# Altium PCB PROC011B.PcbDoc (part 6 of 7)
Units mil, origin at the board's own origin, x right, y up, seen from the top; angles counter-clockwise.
Board outline 3304 x 2569 mil, 6 copper layers (TOP, L2-GND1, L3-GND/SIG, L4-GND/SIG, L5-GND2, BOTTOM), stack 55.77 mil thick; 376 components, 289 nets, 1284 pads, 1755 vias.
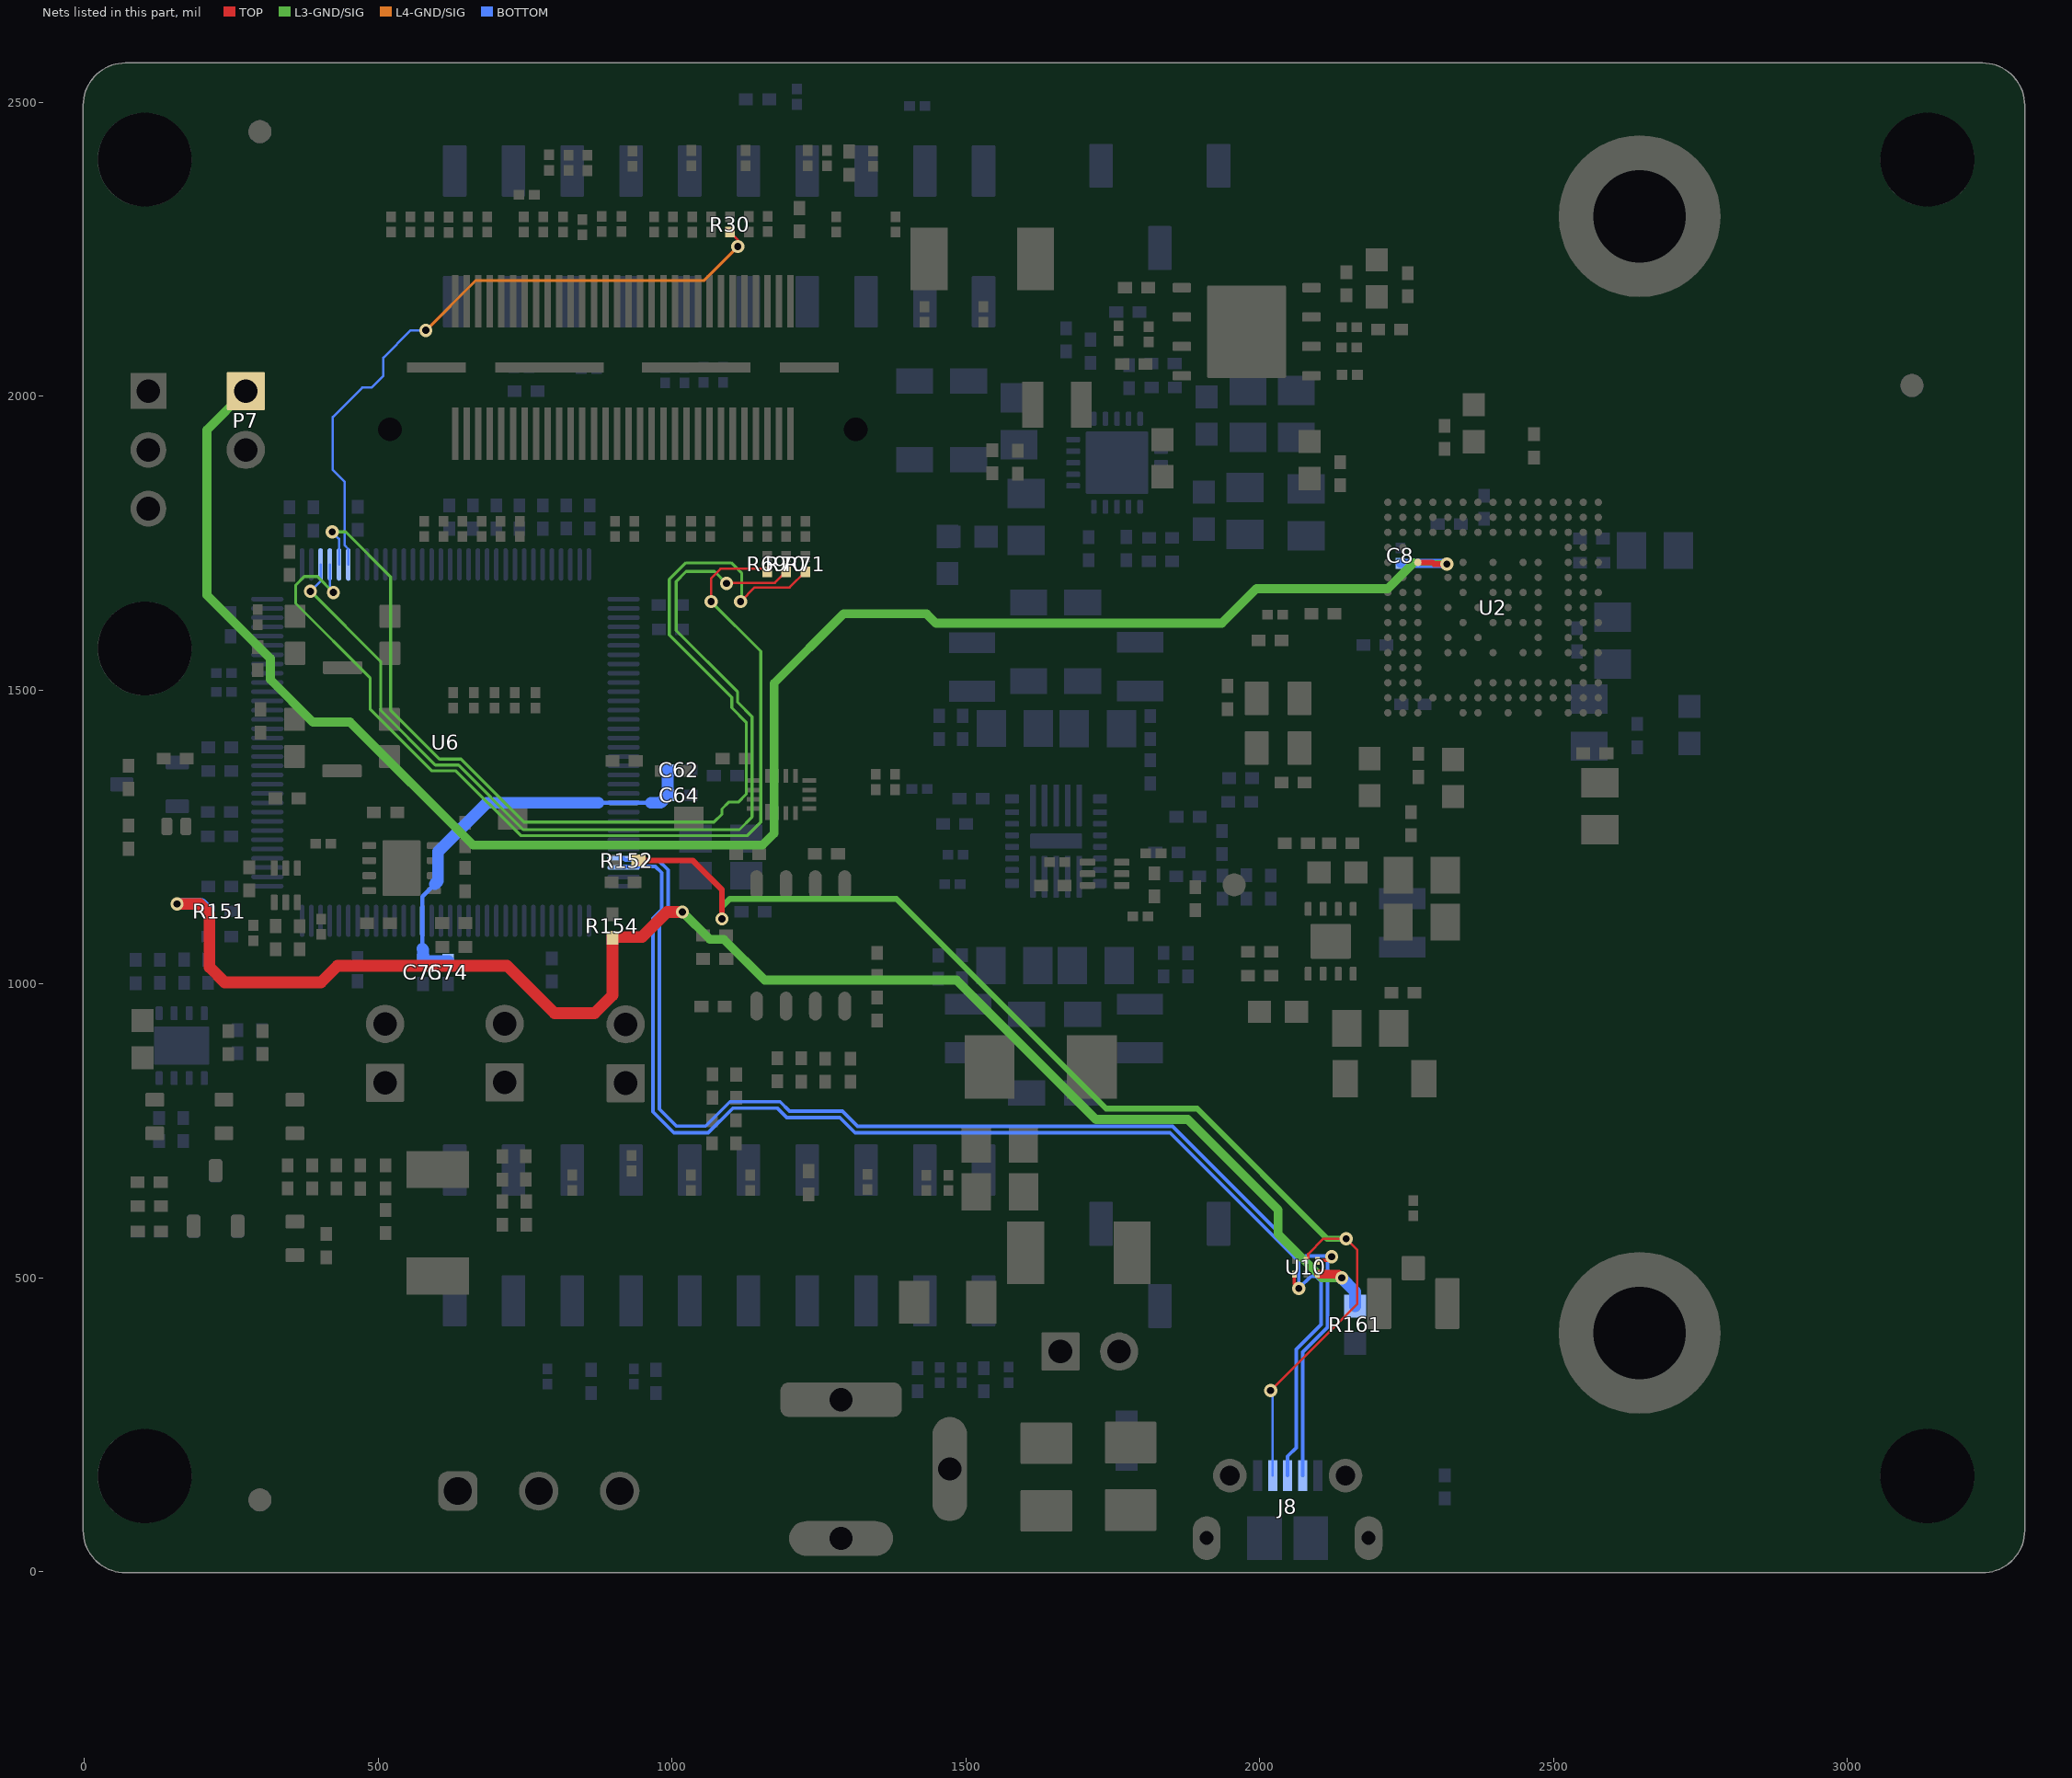
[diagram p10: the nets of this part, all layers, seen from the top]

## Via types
v1: diameter 22.4, hole 12.2, TOP to BOTTOM, tented both sides, 1046 vias
v2: diameter 13.77/15.74 (per signal layer), hole 5.9, TOP to L2-GND1, tented both sides, 699 vias
v3: diameter 19.68, hole 7.87, TOP to BOTTOM, tented both sides, 9 vias
v4: diameter 15.74, hole 5.9, TOP to L2-GND1, tented both sides, 1 vias

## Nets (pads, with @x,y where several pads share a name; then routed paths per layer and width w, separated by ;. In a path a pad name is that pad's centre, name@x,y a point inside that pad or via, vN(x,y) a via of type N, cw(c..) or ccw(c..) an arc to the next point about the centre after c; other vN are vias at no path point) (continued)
VDDC_1: C62.2 C64.2 C74.2 C75.2 U6.87 U6.115 | length 714.8
  BOTTOM w7: 575.17,1059.68 U6.115@575.17,1107.39 575.17,1148.62 596.35,1169.8 ; 874.57,1308.18 U6.87@917.69,1308.18 964.13,1308.18
  BOTTOM w20: 575.17,1059.68 576.43,1058.42 C75.2@576.43,1039.34 576.43,1038.95 C74.2@619.35,1038.95 ; 596.35,1169.8 601.75,1175.2 601.75,1224.9 685.03,1308.18 874.57,1308.18 ; 964.13,1308.18 980.48,1308.18 992.91,1320.61 993.1,1320.8 992.91,1320.99 992.8,1321.1 C62.2@992.8,1364
VPP_1P7: C8.2 P7.1 U2.L13 | length 3174.2
  TOP w10: U2.L13@2269.35,1717.17 2294.02,1717.17 2296.84,1714.35 v1(2318.74,1714.35)
  L3-GND/SIG w10: 2261.95,1716.3 2316.79,1716.3 v1(2318.74,1714.35)
  L3-GND/SIG w15: P7.1@274.69,2008.65 208.57,1942.53 208.57,1661.59 316.55,1553.61 316.55,1517.92 388.87,1445.6 452.05,1445.6 661.45,1236.2 1153.94,1236.2 1173.84,1256.1 1173.84,1511.71 1291.73,1629.6 1433.35,1629.6 1449.15,1613.8 1935.75,1613.8 1994.45,1672.5 2218.15,1672.5 2261.95,1716.3
  BOTTOM w15: C8.2@2239.75,1715.51 2317.59,1715.5 v1(2318.74,1714.35)
XDSET_1_D_N: J8.2 U6.93 U10.1 | length 2199.2
  TOP w5.2: U10.1@2098.44,529.81 2116.56,529.81 v1(2122.75,536)
  BOTTOM w6: U6.93@917.69,1213.69 920.38,1211 976.31,1211 993.45,1193.86 993.45,1121.69 985.21,1113.45 978.75,1106.99 978.75,787 1007.75,758 1057.25,758 1098.75,799.5 1184.01,799.5 1200.01,783.5 1290.31,783.5 1316.11,757.7 1852.05,757.7 2072.75,537 2121.75,537 v1(2122.75,536) 2115.75,529 2115.75,416 2073.34,373.59 J8.2@2073.34,163.38
XDSET_1_D_P: J8.3 U6.94 U10.4 | length 2198.8
  TOP w5.2: U10.4@2059.07,506.19 2059.06,489.69 v1(2066.75,482)
  BOTTOM w6: U6.94@917.69,1197.94 919.75,1200 971.75,1200 982.45,1189.3 982.45,1126.25 967.75,1111.55 967.75,782.44 1003.19,747 1061.81,747 1103.31,788.5 1179.45,788.5 1195.45,772.5 1285.75,772.5 1311.55,746.7 1847.49,746.7 2066.75,527.44 v1(2066.75,482) 2087.25,502.5 2095.75,502.5 2104.75,493.5 2104.75,420.56 2062.34,378.15 2062.34,210.8 2047.75,196.21 J8.3@2047.75,163.38
XDSET_1_ID: J8.4 R152.2 U10.2 | length 2101
  TOP w4: v1(2018.75,308) 2165.85,455.1 2165.85,547.9 v1(2147.25,566.5) 2108.75,566.5 2082.75,540.5 2082.75,533.81 U10.2@2078.75,529.81
  TOP w10: R152.2@942.99,1210 1035.15,1210 1084.95,1160.2 v1(1084.95,1110.55)
  L3-GND/SIG w10: v1(1084.95,1110.55) 1084.95,1131.2 1098.35,1144.6 1381.85,1144.6 1738.75,787.7 1893.55,787.7 2114.75,566.5 v1(2147.25,566.5)
  BOTTOM w4: v1(2018.75,308) 2022.16,304.59 J8.4@2022.16,163.38
XDSET_1_VBUS: R151.2 R154.2 R161.2 U10.6 | length 2710.2
  TOP w10: U10.6@2098.44,506.19 U10.6@2100.25,506.19
  TOP w15: U10.6@2100.25,506.19 2134.56,506.19 2137.75,503 2137.75,500 v1(2139.75,500)
  TOP w20: v1(157.75,1136) 196.05,1136 213.05,1119 213.05,1028.5 238.85,1002.7 402.65,1002.7 430.95,1031 719.35,1031 800.25,950.1 868.15,950.1 898.75,980.7 R154.2@898.75,1078.81 898.75,1079.6 948.65,1079.6 991.55,1122.5 v1(1017.75,1122.5)
  L3-GND/SIG w15: v1(1017.75,1122.5) 1064.4,1075.85 1088.4,1075.85 1157.75,1006.5 1484.35,1006.5 1721.35,769.5 1877.71,769.5 2031.75,615.46 2031.75,574.06 2105.81,500 v1(2139.75,500)
  BOTTOM w20: v1(157.75,1136) 199.04,1136 211.11,1123.93 R151.2@211.5,1123.54 ; v1(2139.75,500) 2139.25,500 2139.5,499.75 2162.75,476.5 R161.2@2162.75,451.5
XDSET_TCK: R70.2 U6.35 | length 1694.7
  TOP w4: v1(1092.75,1681.5) 1093.75,1682.5 1175.35,1682.5 R70.2@1194.08,1701.23
  L3-GND/SIG w5: v1(384.75,1668) 504.35,1548.4 504.35,1465.5 597.35,1372.5 636.75,1372.5 746.75,1262.5 1114.72,1262.5 1136.35,1284.13 1136.35,1454.64 1111.84,1479.15 1111.84,1496.5 1007.05,1601.29 1007.05,1684.8 1023.96,1701.71 1072.54,1701.71 v1(1092.75,1681.5)
  BOTTOM w4: v1(384.75,1668) 401.94,1685.19 U6.35@401.94,1713.69
XDSET_TDI: R30.2 U6.38 | length 1119.7
  TOP w4: R30.2@1098.5,2279.23 1112.15,2265.58 v1(1112.15,2254.6)
  L4-GND/SIG w5: v1(581.15,2112.1) 665.65,2196.6 1054.15,2196.6 v1(1112.15,2254.6)
  BOTTOM w4: U6.38@449.19,1713.69 449.19,1740.05 442.75,1746.49 442.75,1854.5 422.75,1874.5 422.75,1964.5 472.75,2014.5 488.75,2014.5 508.75,2034.5 508.75,2065.3 555.55,2112.1 v1(581.15,2112.1)
XDSET_TDO: R71.2 U6.37 | length 1869.3
  TOP w4: v1(1116.75,1650.5) 1140.75,1674.5 1200.35,1674.5 R71.2@1227.08,1701.23
  L3-GND/SIG w5: v1(421.75,1769) 444.85,1769 521.15,1692.7 521.15,1465.7 604.35,1382.5 640.95,1382.5 748.05,1275.4 1071.6,1275.4 1084.95,1288.75 1084.95,1297.62 1096.49,1309.16 1112.81,1309.16 1126.35,1322.7 1126.35,1445.26 1101.84,1469.77 1101.84,1487.48 995.55,1593.77 995.55,1688.3 1023.75,1716.5 1100.74,1716.5 1118.75,1698.49 1118.75,1652.5 v1(1116.75,1650.5)
  BOTTOM w4: v1(421.75,1769) 433.44,1757.31 U6.37@433.44,1713.69
XDSET_TMS: R69.2 U6.36 | length 1712.2
  TOP w4: v1(1066.75,1650.5) 1066.75,1690.39 1082.56,1706.2 1157.03,1706.2 R69.2@1162,1701.23
  L3-GND/SIG w5: v1(423.75,1666) 396.65,1693.1 374.35,1693.1 359.65,1678.4 359.65,1647.5 486.25,1520.9 486.25,1467.8 591.55,1362.5 632.55,1362.5 742.55,1252.5 1128.43,1252.5 1151.24,1275.31 1151.24,1566.01 v1(1066.75,1650.5)
  BOTTOM w4: U6.36@417.69,1713.69 417.69,1672.06 v1(423.75,1666)
pads on no net: FID1.1 FID2.1 FID3.1 FID4.1 FID5.1 FID6.1 FID7.1 J1.20 J1.22 J1.32 J1.34 J1.38 J1.40 J1.MH1 J1.MH2 J5.7 J5.20 J6.3 J6.11 J8.7 J8.8 LBL1.0 SW1.1 SW1.3 SW2.1 SW2.3 U1. U5.9 U5.17 U5.21@1730.01,1859.46 U5.21@1730.01,1914.18 U5.21@1784.73,1859.46 U5.21@1784.73,1914.18 U6.2 U6.3 U6.4 U6.5 U6.6 U6.11 U6.12 U6.13 U6.14 U6.15 U6.18 U6.19 U6.20 U6.21 U6.22 U6.23 U6.24 U6.27 U6.29 U6.30 U6.31 U6.32 U6.41 U6.42 U6.43 U6.44 U6.45 U6.46 U6.49 U6.50 U6.53 U6.54 U6.56 U6.57 U6.65 U6.67 U6.71 U6.72 U6.73 U6.74 U6.75 U6.76 U6.77 U6.78 U6.81 U6.82 U6.83 U6.84 U6.85 U6.86 U6.91 U6.92 U6.97 U6.98 U6.99 U6.100 U6.102 U6.103 U6.104 U6.105 U6.106 U6.107 U6.108 U6.109 U6.110 U6.111 U6.112 U6.116 U6.117 U6.118 U6.119 U6.120 U6.121 U6.123 U6.124 U6.125 U6.126 U6.127 U6.128 U7.3 U8. U9.7 U11.7 U14.9 U14.12

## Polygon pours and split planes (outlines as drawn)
no net on Top Solder (solid): 1698.75,2487 1698.75,2382 2076.75,2382 2076.75,2309 2460.75,2309 2460.75,2487 1698.75,2487
no net on Top Solder (solid): 87 vertices, not listed, extent 2360.75,777.5 3282.75,1912.5
no net on Top Solder (solid): 2060.78,2172.88 2112.88,2172.88 2112.88,2196.48 2060.78,2196.48 2060.78,2172.88
no net on Top Solder (solid): 2060.78,2122.88 2112.88,2122.88 2112.88,2146.48 2060.78,2146.48 2060.78,2122.88
no net on Top Solder (solid): 2060.78,2072.88 2112.88,2072.88 2112.88,2096.48 2060.78,2096.48 2060.78,2072.88
no net on Top Solder (solid): 1842.88,2172.88 1894.98,2172.88 1894.98,2196.48 1842.88,2196.48 1842.88,2172.88
no net on Top Solder (solid): 1842.88,2122.88 1894.98,2122.88 1894.98,2146.48 1842.88,2146.48 1842.88,2122.88
no net on Top Solder (solid): 1842.88,2022.88 1894.98,2022.88 1894.98,2046.48 1842.88,2046.48 1842.88,2022.88
no net on Top Solder (solid): 2060.78,2022.88 2112.88,2022.88 2112.88,2046.48 2060.78,2046.48 2060.78,2022.88
no net on Top Solder (solid): 1842.88,2072.88 1894.98,2072.88 1894.98,2096.48 1842.88,2096.48 1842.88,2072.88
no net on Bottom Solder (solid): 72 vertices, not listed, extent 2093.75,17.5 3284.85,1693.5
GND on TOP "TOP-GND 1" (solid, remove dead copper, pour order 1007): 2460.75,2487 2460.75,2309 2076.75,2309 2076.75,2382 1698.75,2382 1698.75,2487 2460.75,2487
no net on TOP "Top Layer-No Net" (solid, pour order 956): 2211.13,2344.45 2211.13,2350.35 2222.94,2350.35 2246.56,2350.94 2394.35,2350.94 2417.97,2350.35 2429.78,2350.35 2429.78,2344.45 2417.97,2344.45 2394.35,2343.86 2246.56,2343.86 2222.94,2344.45
no net on TOP "Top Layer-No Net" (solid, pour order 951): 1734.28,2432.55 1746.09,2432.55 1769.71,2431.96 2395.15,2431.96 2418.77,2432.55 2430.58,2432.55 2430.58,2438.45 2418.77,2438.45 2395.15,2439.04 1769.71,2439.04 1746.09,2438.45 1734.28,2438.45
RX4 on TOP "TOP-RX4" (solid, pour order 948): 38 vertices, not listed, extent 2736.95,1524.17 3184.98,1583.23
RX3 on TOP "TOP-RX3" (solid, pour order 949): 38 vertices, not listed, extent 2736.95,1598.97 3184.98,1658.03
RX2 on TOP "TOP-RX2" (solid, pour order 950): 38 vertices, not listed, extent 2736.95,1673.77 3184.98,1732.83
RX1 on TOP "TOP-RX1" (solid, pour order 952): 38 vertices, not listed, extent 2736.95,1748.57 3184.98,1807.63
GND on TOP "TOP-GND 4" (solid, pour order 978): 38 vertices, not listed, extent 2736.95,1449.37 3184.98,1508.43
GND on TOP "TOP-GND 5" (solid, pour order 981): 38 vertices, not listed, extent 2736.95,1823.37 3184.98,1882.43
PMIC_1V2 on TOP "TOP-PMIC_1V2" (solid, pour order 979): 40 vertices, not listed, extent 1988.35,1837.9 2151.05,1900.5
TX2 on TOP "TOP-TX2" (solid, remove dead copper, pour order 1043): 38 vertices, not listed, extent 2736.95,873.67 3184.98,932.73
TX1 on TOP "TOP-TX1" (solid, pour order 1042): 38 vertices, not listed, extent 2736.95,1172.87 3184.98,1231.93
NetC26_1 on TOP "TOP-UNNAMED_39_CAPPOLARIZED_I74_1" (solid, pour order 953): 340 vertices, not listed, extent 1471.05,182.8 1838.25,913.5
NetC85_2 on TOP "TOP-UNNAMED_7_CAPNONPOLARIZED_I5_2" (solid, pour order 954): 194 vertices, not listed, extent 384.65,1079 496.19,1218
PMIC_2V3 on TOP "TOP-PMIC_2V3" (solid, pour order 957): 258 vertices, not listed, extent 1843.65,791.5 2266.05,1059.2
MCU_5V on TOP "TOP-MCU_5V" (solid, pour order 962): 124 vertices, not listed, extent 521.77,668 690.75,772
NetF1_2 on TOP "TOP-UNNAMED_39_FUSE_I161_1" (solid, pour order 965): 146 vertices, not listed, extent 1188.75,269 1438.25,500
NetJ1_1 on TOP "TOP-UNNAMED_43_QSH03001XD_I1_1" (solid, pour order 966): 466 vertices, not listed, extent 1177.39,1891 1453.7,2296
NetR40_1 on TOP "TOP-UNNAMED_41_RESISTOR_I120_1" (solid, pour order 967): 2112.88,2146.48 2060.78,2146.48 2060.78,2122.88 2112.88,2122.88 2112.88,2146.48
NetR39_2 on TOP "TOP-UNNAMED_41_RESISTOR_I119_2" (solid, pour order 968): 1894.98,2146.48 1842.88,2146.48 1842.88,2122.88 1894.98,2122.88 1894.98,2146.48
NetR45_1 on TOP "TOP-UNNAMED_41_RESISTOR_I118_1" (solid, pour order 969): 2112.88,2046.48 2060.78,2046.48 2060.78,2022.88 2112.88,2022.88 2112.88,2046.48
NetR44_1 on TOP "TOP-UNNAMED_41_RESISTOR_I117_1" (solid, pour order 970): 2112.88,2096.48 2060.78,2096.48 2060.78,2072.88 2112.88,2072.88 2112.88,2096.48
NetR42_2 on TOP "TOP-UNNAMED_41_RESISTOR_I116_2" (solid, pour order 971): 1894.98,2096.48 1842.88,2096.48 1842.88,2072.88 1894.98,2072.88 1894.98,2096.48
PMIC_1V8 on TOP "TOP-PMIC_1V8" (solid, pour order 972): 210 vertices, not listed, extent 1584.35,1792.5 1702.75,2024.9
AR_VOUT_PA on TOP "TOP-AR_VOUT_PA" (solid, pour order 975): 190 vertices, not listed, extent 2536.75,1315 2648.75,1493.98
AR_QSPI_CS on TOP "TOP-AR_QSPI_CS" (solid, pour order 977): 1894.98,2196.48 1842.88,2196.48 1842.88,2172.88 1894.98,2172.88 1894.98,2196.48
PMIC_1V2 on TOP "TOP-PMIC_1V2 1" (solid, pour order 980): 198 vertices, not listed, extent 2449.77,1853.5 2499.73,1918.5
PMIC_1V2 on TOP "TOP-PMIC_1V2 2" (solid, pour order 982): 96 vertices, not listed, extent 2121.75,1611.72 2223.75,1643.18
AR_1V8 on TOP "TOP-AR_1V8" (solid, pour order 985): 271 vertices, not listed, extent 2126.75,1077.5 2272.75,1307.5
AR_1P3_RF2 on TOP "TOP-AR_1P3_RF2" (solid, pour order 989): 213 vertices, not listed, extent 1679.85,1912.5 1887.75,2027.5
AR_1P3_RF1 on TOP "TOP-AR_1P3_RF1" (solid, pour order 991): 98 vertices, not listed, extent 1812.75,1782.5 1887.75,1877.5
5V_IN on TOP "TOP-5V_IN" (solid, pour order 993): 140 vertices, not listed, extent 439.65,1204 503.85,1307
5V_IN on TOP "TOP-5V_IN 1" (solid, pour order 994): 178 vertices, not listed, extent 1601.75,2177.75 1764.75,2365
5V_IN on TOP "TOP-5V_IN 2" (solid, pour order 995): 98 vertices, not listed, extent 511.75,336 769.75,518.6
5V_IN on TOP "TOP-5V_IN 3" (solid, remove dead copper, pour order 996): 169 vertices, not listed, extent 1558.65,336.3 1705.75,763.3
NetC1_2 on TOP "TOP-UNNAMED_41_CAPNONPOLARIZED_I63_" (solid, pour order 998): 2112.88,2196.48 2060.78,2196.48 2060.78,2172.88 2112.88,2172.88 2112.88,2196.48
5V_UNREG on TOP "TOP-5V_UNREG" (solid, pour order 1000): 122 vertices, not listed, extent 1729.45,342.3 1860.45,608.8
GND on TOP "TOP-GND" (solid, pour order 1006): 1894.98,2046.48 1842.88,2046.48 1842.88,2022.88 1894.98,2022.88 1894.98,2046.48
GND on TOP "TOP-GND 6" (solid, pour order 1014): 234 vertices, not listed, extent 1721.35,1161.1 1753.05,1226.6
GND on TOP "TOP-GND 7" (solid, pour order 1015): 162 vertices, not listed, extent 306.05,1160.99 369.63,1183.3
GND on TOP "TOP-GND 8" (solid, pour order 1016): 114 vertices, not listed, extent 1639.05,670 1773.15,928.2
GND on TOP "TOP-GND 9" (solid, pour order 1030): 217 vertices, not listed, extent 2250.67,1162.5 2332.75,1262.5
GND on TOP "TOP-GND 10" (solid, pour order 1031): 247 vertices, not listed, extent 187.75,1417.5 477.4,1552.5
GND on TOP "TOP-GND 11" (solid, pour order 1032): 146 vertices, not listed, extent 507.65,1089 572.15,1306
GND on TOP "TOP-GND 12" (solid, pour order 1036): 170 vertices, not listed, extent 1193.75,39 1828.75,265
GND on TOP "TOP-GND 14" (solid, pour order 1038): 72 vertices, not listed, extent 2573.71,1808.32 2613.84,1842.2
+3.3VD on TOP "TOP-+3.3VD" (solid, pour order 1041): 173 vertices, not listed, extent 2302.45,1845.65 2382.74,1941.4
GND on TOP "TOP-GND 3" (solid, remove dead copper, pour order 974): 2501.25,2155.5 2800.25,2155.5 2800.25,2457.5 2501.25,2457.5 2501.25,2155.5
GND on TOP "TOP-GND 13" (solid, remove dead copper, pour order 1044): 2847 vertices, not listed, extent 2201.45,15.1 3284.75,2549.4
GND on L4-GND/SIG "Top Layer-No Net" (solid, pour order 116): 43 vertices, not listed, extent 1376.03,1265.26 1898.12,2227.86
5V_UNREG on L4-GND/SIG "POWER2-No Net" (solid, remove dead copper, pour order 1046): 44 vertices, not listed, extent 1441.77,315 1865.48,1542.5
NetC85_2 on L4-GND/SIG "L4-UNNAMED_7_CAPNONPOLARIZED_I5_2" (solid, pour order 955): 96 vertices, not listed, extent 371.65,1146.2 422.25,1236.1
PMIC_1V2 on L4-GND/SIG "L4-PMIC_1V2" (solid, pour order 984): 1509 vertices, not listed, extent 1750.75,1574 2517.75,2258.4
AR_1V8 on L4-GND/SIG "L4-AR_1V8" (solid, pour order 986): 679 vertices, not listed, extent 2127.75,1077.15 2619.75,1752
5V_IN on L4-GND/SIG "L4-5V_IN" (solid, remove dead copper, pour order 997): 1026 vertices, not listed, extent 437.25,327 1727.75,2363.5
GND on L4-GND/SIG "L4-GND" (solid, pour order 1019): 555 vertices, not listed, extent 486.77,2124.33 1041.63,2468.58
GND on L4-GND/SIG "L4-GND 1" (solid, pour order 1020): 840 vertices, not listed, extent 2279.76,1480.82 2511.89,1757.58
GND on L4-GND/SIG "L4-GND 3" (solid, remove dead copper, pour order 1022): 2496 vertices, not listed, extent 16,16 3284,2549
GND on L4-GND/SIG "L4-GND 4" (solid, pour order 1023): 1170 vertices, not listed, extent 1011,2201.12 1728.04,2476.59
PMIC_2V3 on BOTTOM "BOTTOM-PMIC_2V3" (solid, pour order 958): 127 vertices, not listed, extent 1662.75,791 1947.35,900.66
PMIC_2V3 on BOTTOM "BOTTOM-PMIC_2V3 1" (solid, pour order 960): 146 vertices, not listed, extent 2140.55,968.7 2284.45,1079.3
MCU_5V on BOTTOM "BOTTOM-MCU_5V" (solid, pour order 961): 149 vertices, not listed, extent 517.75,626.5 686.75,759.5
MCU_5V on BOTTOM "BOTTOM-MCU_5V 1" (solid, pour order 964): 98 vertices, not listed, extent 1868.75,510 1993.75,651
PMIC_1V8 on BOTTOM "BOTTOM-PMIC_1V8" (solid, remove dead copper, pour order 973): 1183 vertices, not listed, extent 1339.97,801.5 1702.75,1952.5
AR_VOUT_PA on BOTTOM "BOTTOM-AR_VOUT_PA" (solid, pour order 976): 138 vertices, not listed, extent 2539.75,1315 2755.75,1427
PMIC_1V2 on BOTTOM "BOTTOM-PMIC_1V2" (solid, pour order 983): 299 vertices, not listed, extent 1663,1563 1950.75,1709.25
AR_1V8 on BOTTOM "BOTTOM-AR_1V8" (solid, pour order 987): 91 vertices, not listed, extent 2526.75,1593 2629.75,1638.98
AR_1V8 on BOTTOM "BOTTOM-AR_1V8 1" (solid, pour order 988): 124 vertices, not listed, extent 2147.75,1120 2286.65,1256.3
AR_1P3_RF2 on BOTTOM "BOTTOM-AR_1P3_RF2" (solid, pour order 990): 1059 vertices, not listed, extent 1818.8,1431.4 2987.75,2118
AR_1P3_RF1 on BOTTOM "BOTTOM-AR_1P3_RF1" (solid, pour order 992): 937 vertices, not listed, extent 1821.75,1607 2812.73,1963.7
PMICOUT_3V3 on BOTTOM "BOTTOM-PMICOUT_3V3" (solid, pour order 999): 176 vertices, not listed, extent 1453.77,1563.04 1642.75,1711.5
5V_UNREG on BOTTOM "BOTTOM-5V_UNREG" (solid, remove dead copper, pour order 1002): 183 vertices, not listed, extent 1514.45,1002.3 1620.75,1218.3
5V_UNREG on BOTTOM "BOTTOM-5V_UNREG 1" (solid, pour order 1003): 202 vertices, not listed, extent 1686.8,1002.3 1813.8,1218.5
5V_UNREG on BOTTOM "BOTTOM-5V_UNREG 2" (solid, pour order 1004): 209 vertices, not listed, extent 1687.75,1267.5 1787.85,1475.66
5V_UNREG on BOTTOM "BOTTOM-5V_UNREG 3" (solid, pour order 1005): 200 vertices, not listed, extent 1525.15,1267.5 1619.3,1475.26
GND on BOTTOM "BOTTOM-GND" (solid, pour order 1008): 21 vertices, not listed, extent 2421.7,31.02 3277.75,827.5
GND on BOTTOM "BOTTOM-GND 1" (solid, pour order 1013): 2497.25,2153.5 2796.25,2153.5 2796.25,2455.5 2497.25,2455.5 2497.25,2153.5
GND on BOTTOM "BOTTOM-GND 2" (solid, pour order 1033): 124 vertices, not listed, extent 1364.75,1971.5 1621.05,2069.85
GND on BOTTOM "BOTTOM-GND 3" (solid, pour order 1034): 510 vertices, not listed, extent 1703,307 2093.73,726.5
GND on BOTTOM "BOTTOM-GND 5" (solid, pour order 1037): 98 vertices, not listed, extent 1882.75,1982.35 2102.75,2147.5
GND on BOTTOM "BOTTOM-GND 6" (solid, pour order 1039): 239 vertices, not listed, extent 1567.7,919.3 1734.3,1218.3
GND on BOTTOM "BOTTOM-GND 7" (solid, pour order 1040): 307 vertices, not listed, extent 1568.8,1267.5 1736.9,1546
GND on BOTTOM "BOTTOM-GND 4" (solid, remove dead copper, pour order 1035): 2173 vertices, not listed, extent 1878.77,15.7 3284.85,2549.9
MCU_5V on L3-GND/SIG "L3-MCU_5V" (solid, pour order 963): 517 vertices, not listed, extent 507.75,406 1962.23,755.48
GND on L3-GND/SIG "L3-GND" (solid, pour order 1011): 2507.75,2437.5 2777.75,2437.5 2777.75,2182.5 2597.75,2182.5 2507.75,2272.5 2507.75,2437.5
GND on L3-GND/SIG "L3-GND 1" (solid, pour order 1012): 2487.75,562.5 2787.75,562.5 2787.75,262.5 2487.75,262.5 2487.75,562.5
GND on L3-GND/SIG "L3-GND 2" (solid, pour order 1024): 146 vertices, not listed, extent 1858.06,1991.53 2249.71,2152.58
GND on L3-GND/SIG "L3-GND 3" (solid, pour order 1025): 344 vertices, not listed, extent 1505.88,1776.02 1989.21,2041.98
GND on L3-GND/SIG "L3-GND 4" (solid, pour order 1026): 147 vertices, not listed, extent 231.09,1463.5 468.73,1691.74
GND on L3-GND/SIG "L3-GND 5" (solid, pour order 1027): 744 vertices, not listed, extent 991.89,593.02 1910.98,1006.2
GND on L3-GND/SIG "L3-GND 6" (solid, pour order 1028): 2622 vertices, not listed, extent 1431.33,501.13 2744.73,1845.59
GND on L3-GND/SIG "L3-GND 7" (solid, remove dead copper, pour order 1029): 3094 vertices, not listed, extent 16,16 3284,2549
GND on L2-GND1 "L5-GND" (solid, remove dead copper, pour order 1018): 553 vertices, not listed, extent 16,16 3284,2549
GND on L2-GND1 "L2-GND" (solid, pour order 1009): 2524.75,2427 2524.75,2180 2769.75,2180 2769.75,2427 2524.75,2427
GND on L2-GND1 "L2-GND 1" (solid, pour order 1010): 2527.25,529.5 2527.25,282.5 2772.25,282.5 2772.25,529.5 2527.25,529.5
GND on L5-GND2 "L5-GND" (solid, remove dead copper, pour order 1017): 553 vertices, not listed, extent 16,16 3284,2549
no net on Mechanical 6 Ass bot (solid): 340.75,2450 ccw(c298.75,2450) 298.75,2492 ccw(c298.75,2450) 256.75,2450 ccw(c298.75,2450) 298.75,2408 ccw(c298.75,2450) 340.75,2450
no net on Mechanical 6 Ass bot (solid): 340.75,122 ccw(c298.75,122) 298.75,164 ccw(c298.75,122) 256.75,122 ccw(c298.75,122) 298.75,80 ccw(c298.75,122) 340.75,122
no net on Mechanical 6 Ass bot (solid): 3150.95,2033.2 ccw(c3108.95,2033.2) 3108.95,2075.2 ccw(c3108.95,2033.2) 3066.95,2033.2 ccw(c3108.95,2033.2) 3108.95,1991.2 ccw(c3108.95,2033.2) 3150.95,2033.2
no net on Mechanical 5 Ass top (solid): 340.75,122 ccw(c298.75,122) 298.75,164 ccw(c298.75,122) 256.75,122 ccw(c298.75,122) 298.75,80 ccw(c298.75,122) 340.75,122
no net on Mechanical 5 Ass top (solid): 3152.65,2018.46 ccw(c3110.65,2018.46) 3110.65,2060.46 ccw(c3110.65,2018.46) 3068.65,2018.46 ccw(c3110.65,2018.46) 3110.65,1976.46 ccw(c3110.65,2018.46) 3152.65,2018.46
no net on Mechanical 5 Ass top (solid): 340.75,2450 ccw(c298.75,2450) 298.75,2492 ccw(c298.75,2450) 256.75,2450 ccw(c298.75,2450) 298.75,2408 ccw(c298.75,2450) 340.75,2450

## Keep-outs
TOP:
  circle w10: c3136.31,162.5 r92.09
  circle w10: c3136.31,2402.5 r92.09
  circle w10: c102.75,162.5 r92.09
  circle w10: c102.75,1570.6 r92.09
  circle w10: c102.75,2402.5 r92.09
L2-GND1:
  circle w10: c520.13,1943.64 r44.95
  circle w10: c1312.65,1943.64 r44.95
  circle w10: c3136.31,2402.5 r100.82
  circle w10: c3136.31,162.5 r100.82
  circle w10: c3136.31,2402.5 r100.82
L3-GND/SIG:
  circle w10: c3136.31,2402.5 r100.82
  circle w10: c3136.31,162.5 r100.82
L4-GND/SIG:
  circle w10: c3136.31,2402.5 r100.82
  circle w10: c3136.31,162.5 r100.82
  circle w10: c1312.65,1943.64 r44.95
L5-GND2:
  circle w10: c3136.31,162.5 r100.82
  circle w10: c3136.31,2402.5 r100.82
  circle w10: c520.13,1943.64 r44.95
  circle w10: c1312.65,1943.64 r44.95
BOTTOM:
  circle w1: c3110.08,2018.14 r44
  circle w10: c3136.31,2402.5 r92.09
  circle w10: c3136.31,162.5 r92.09
Keep-Out Layer:
  text "KEEP OUT LAYER" at -1318.01,-1032.33 h75

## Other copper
TOP:
  pour cut-out: 2207.19,2340.51 2207.19,2354.29 2222.94,2354.29 2246.56,2357.65 2394.35,2357.65 2417.97,2354.29 2433.72,2354.29 2433.72,2340.51 2417.97,2340.51 2394.35,2337.15 2246.56,2337.15 2222.94,2340.51
  pour cut-out: 1730.34,2428.61 1730.34,2442.39 1746.09,2442.39 1769.71,2445.75 2395.15,2445.75 2418.77,2442.39 2434.52,2442.39 2434.52,2428.61 2418.77,2428.61 2395.15,2425.25 1769.71,2425.25 1746.09,2428.61
  pour cut-out: 2611.75,1286.5 2546.75,1286.5 2546.75,1309 2611.75,1309
  pour cut-out: 2566.95,1640.4 2565.72,1646.56 2562.23,1651.79 2557,1655.28 2550.84,1656.51 2544.68,1655.28 2539.45,1651.79 2535.96,1646.56 2534.73,1640.4 2535.96,1634.24 2539.45,1629.01 2544.68,1625.52 2550.84,1624.29 2557,1625.52 2562.23,1629.01 2565.72,1634.24 2566.95,1640.4
  pour cut-out: 2566.95,1691.58 2565.72,1697.74 2562.23,1702.97 2557,1706.46 2550.84,1707.69 2544.68,1706.46 2539.45,1702.97 2535.96,1697.74 2534.73,1691.58 2535.96,1685.42 2539.45,1680.19 2544.68,1676.7 2550.84,1675.47 2557,1676.7 2562.23,1680.19 2565.72,1685.42 2566.95,1691.58
  pour cut-out: 2566.95,1742.76 2565.72,1748.92 2562.23,1754.15 2557,1757.64 2550.84,1758.87 2544.68,1757.64 2539.45,1754.15 2535.96,1748.92 2534.73,1742.76 2535.96,1736.6 2539.45,1731.37 2544.68,1727.88 2550.84,1726.65 2557,1727.88 2562.23,1731.37 2565.72,1736.6 2566.95,1742.76
  pour cut-out: 2566.95,1589.22 2565.72,1595.38 2562.23,1600.61 2557,1604.1 2550.84,1605.33 2544.68,1604.1 2539.45,1600.61 2535.96,1595.38 2534.73,1589.22 2535.96,1583.06 2539.45,1577.83 2544.68,1574.34 2550.84,1573.11 2557,1574.34 2562.23,1577.83 2565.72,1583.06 2566.95,1589.22
  pour cut-out: 2515.77,1486.86 2514.54,1493.02 2511.05,1498.25 2505.82,1501.74 2499.66,1502.97 2493.5,1501.74 2488.27,1498.25 2484.78,1493.02 2483.55,1486.86 2484.78,1480.7 2488.27,1475.47 2493.5,1471.98 2499.66,1470.75 2505.82,1471.98 2511.05,1475.47 2514.54,1480.7 2515.77,1486.86
  pour cut-out: 2445.48,1783.84 2447.64,1781.68 2443.69,1777.72 2443.38,1777.55 2442.6,1777.07 2441.86,1776.53 2441.17,1775.92 2440.54,1775.25 2439.97,1774.53 2439.46,1773.77 2439.02,1772.96 2438.66,1772.12 2438.57,1771.88 2438.38,1771.35 2436.22,1769.19 2432.26,1773.14 2432.09,1773.45 2431.61,1774.23 2431.06,1774.97 2430.45,1775.65 2429.78,1776.29 2429.07,1776.86 2428.84,1777.02 2428.84,1777.03 2428.5,1777.29 2428.17,1777.58 2427.87,1777.9 2427.6,1778.24 2427.37,1778.61 2427.16,1778.99 2426.99,1779.39 2426.85,1779.81 2426.75,1780.23 2426.69,1780.66 2426.67,1781.1 2426.68,1781.54 2426.74,1781.97 2426.83,1782.4 2426.95,1782.81 2427.12,1783.22 2427.31,1783.61 2427.55,1783.98 2427.81,1784.32 2428.1,1784.65 2428.42,1784.95 2428.76,1785.22 2428.84,1785.27 2429.57,1785.82 2430.25,1786.44 2430.88,1787.11 2431.45,1787.83 2431.95,1788.6 2432.38,1789.41 2432.74,1790.25 2432.8,1790.41 2432.99,1790.94 2435.15,1793.1 2439.11,1789.15 2439.28,1788.84 2439.76,1788.06 2440.3,1787.32 2440.91,1786.63 2441.58,1786 2442.3,1785.43 2443.06,1784.92 2443.87,1784.48 2444.71,1784.12 2444.95,1784.03 2445.48,1783.84
  pour cut-out: 2416.94,1785.27 2417.29,1785.01 2417.61,1784.72 2417.91,1784.4 2418.18,1784.05 2418.42,1783.69 2418.62,1783.3 2418.79,1782.9 2418.93,1782.49 2419.03,1782.06 2419.09,1781.63 2419.11,1781.19 2419.09,1780.76 2419.04,1780.33 2418.95,1779.9 2418.82,1779.48 2418.66,1779.08 2418.46,1778.69 2418.23,1778.32 2417.97,1777.97 2417.68,1777.65 2417.36,1777.35 2417.01,1777.08 2416.94,1777.02 2416.2,1776.47 2415.52,1775.86 2414.89,1775.19 2414.43,1774.6 2414.16,1774.26 2413.85,1773.95 2413.53,1773.66 2413.17,1773.4 2412.8,1773.18 2412.41,1772.99 2412,1772.83 2411.58,1772.71 2411.15,1772.63 2410.72,1772.58 2410.28,1772.57 2409.85,1772.6 2409.42,1772.67 2408.99,1772.77 2408.58,1772.92 2408.18,1773.09 2407.8,1773.3 2407.44,1773.55 2407.1,1773.82 2406.87,1774.04 2402.55,1778.36 2400.54,1778.36 2400.2,1778.46 2399.31,1778.68 2399.25,1778.69 2399.04,1778.74 2398.83,1778.81 2398.63,1778.9 2398.44,1779 2398.25,1779.12 2398.08,1779.25 2397.92,1779.4 2397.78,1779.56 2397.65,1779.74 2397.53,1779.92 2397.43,1780.12 2397.35,1780.32 2397.29,1780.53 2397.24,1780.74 2397.22,1780.96 2397.21,1781.18 2397.22,1781.39 2397.25,1781.61 2397.3,1781.82 2397.37,1782.03 2397.46,1782.23 2397.56,1782.42 2397.68,1782.61 2397.81,1782.78 2397.96,1782.94 2398.12,1783.08 2398.3,1783.21 2398.48,1783.33 2398.68,1783.43 2398.88,1783.51 2399.09,1783.57 2399.25,1783.6 2400.14,1783.81 2401.02,1784.1 2401.86,1784.46 2402.67,1784.89 2403.44,1785.39 2404.16,1785.96 2404.83,1786.59 2405.44,1787.27 2405.99,1788.01 2406.47,1788.79 2406.89,1789.61 2407.21,1790.41 2407.4,1790.94 2409.56,1793.1 2413.52,1789.15 2413.69,1788.84 2414.17,1788.06 2414.72,1787.32 2415.33,1786.64 2416,1786 2416.71,1785.43 2416.94,1785.27
  pour cut-out: 2391.35,1785.27 2391.7,1785.01 2392.02,1784.72 2392.32,1784.4 2392.59,1784.05 2392.83,1783.69 2393.03,1783.3 2393.2,1782.9 2393.34,1782.49 2393.44,1782.06 2393.5,1781.63 2393.52,1781.19 2393.5,1780.76 2393.45,1780.33 2393.36,1779.9 2393.23,1779.48 2393.07,1779.08 2392.87,1778.69 2392.64,1778.32 2392.38,1777.97 2392.09,1777.65 2391.77,1777.35 2391.42,1777.08 2391.35,1777.02 2390.62,1776.47 2389.94,1775.85 2389.31,1775.18 2388.74,1774.46 2388.24,1773.69 2387.81,1772.88 2387.45,1772.04 2387.39,1771.88 2387.2,1771.35 2385.04,1769.19 2381.08,1773.14 2380.91,1773.45 2380.43,1774.23 2379.88,1774.97 2379.27,1775.65 2378.6,1776.29 2377.89,1776.86 2377.66,1777.02 2377.66,1777.03 2377.32,1777.29 2376.99,1777.58 2376.69,1777.9 2376.42,1778.24 2376.19,1778.61 2375.98,1778.99 2375.81,1779.39 2375.67,1779.81 2375.57,1780.23 2375.51,1780.66 2375.49,1781.1 2375.5,1781.54 2375.56,1781.97 2375.65,1782.4 2375.77,1782.81 2375.94,1783.22 2376.13,1783.61 2376.37,1783.98 2376.63,1784.32 2376.92,1784.65 2377.24,1784.95 2377.58,1785.22 2377.66,1785.27 2378.39,1785.82 2379.07,1786.44 2379.7,1787.11 2380.27,1787.83 2380.77,1788.6 2381.2,1789.41 2381.56,1790.25 2381.62,1790.41 2381.81,1790.94 2383.97,1793.1 2387.93,1789.15 2388.1,1788.84 2388.58,1788.06 2389.13,1787.32 2389.74,1786.64 2390.41,1786 2391.12,1785.43 2391.35,1785.27
  pour cut-out: 2365.76,1785.27 2366.11,1785.01 2366.43,1784.72 2366.73,1784.4 2367,1784.05 2367.24,1783.69 2367.44,1783.3 2367.61,1782.9 2367.75,1782.49 2367.85,1782.06 2367.91,1781.63 2367.93,1781.19 2367.91,1780.76 2367.86,1780.33 2367.77,1779.9 2367.64,1779.48 2367.48,1779.08 2367.28,1778.69 2367.05,1778.32 2366.79,1777.97 2366.5,1777.65 2366.18,1777.35 2365.83,1777.08 2365.76,1777.02 2365.03,1776.47 2364.35,1775.85 2363.72,1775.18 2363.15,1774.46 2362.65,1773.69 2362.22,1772.88 2361.86,1772.04 2361.58,1771.16 2361.48,1770.81 2361.32,1770.13 2359.05,1767.86 2356.45,1770.47 2356.27,1771.11 2355.99,1771.98 2355.64,1772.83 2355.21,1773.64 2354.72,1774.42 2354.15,1775.14 2353.53,1775.82 2352.85,1776.43 2352.12,1776.99 2352.07,1777.02 2352.07,1777.03 2351.72,1777.29 2351.4,1777.58 2351.1,1777.9 2350.83,1778.24 2350.6,1778.61 2350.39,1778.99 2350.22,1779.39 2350.08,1779.81 2349.99,1780.23 2349.92,1780.66 2349.9,1781.1 2349.91,1781.54 2349.97,1781.97 2350.06,1782.4 2350.18,1782.81 2350.35,1783.22 2350.54,1783.61 2350.78,1783.98 2351.04,1784.32 2351.33,1784.65 2351.65,1784.95 2351.99,1785.22 2352.07,1785.27 2352.8,1785.82 2353.48,1786.44 2354.11,1787.11 2354.68,1787.83 2355.18,1788.6 2355.61,1789.41 2355.97,1790.25 2356.03,1790.41 2356.22,1790.94 2358.38,1793.1 2362.34,1789.15 2362.51,1788.84 2362.99,1788.06 2363.54,1787.32 2364.15,1786.64 2364.82,1786 2365.53,1785.43 2365.76,1785.27
  pour cut-out: 202 vertices and 0 holes, not listed, extent 2450.64,1723.74 2493.52,1761.38
  pour cut-out: 2464.59,1486.86 2463.36,1493.02 2459.87,1498.25 2454.64,1501.74 2448.48,1502.97 2442.32,1501.74 2437.09,1498.25 2433.6,1493.02 2432.37,1486.86 2433.6,1480.7 2437.09,1475.47 2442.32,1471.98 2448.48,1470.75 2454.64,1471.98 2459.87,1475.47 2463.36,1480.7 2464.59,1486.86
  pour cut-out: 2563.65,1383.05 2577.45,1383.05 2577.45,1401.65 2563.65,1401.65
  pour cut-out: 2577.75,1406 2577.75,1379 2622.75,1379 2629.75,1372 2629.75,1328 2625.75,1324 2570.75,1324 2532.75,1362 2532.75,1500 2537.75,1505 2565.75,1505 2569.75,1501 2569.75,1414 2577.75,1406
  text "TOP" at -1316.15,-1038.69 h75
L2-GND1:
  pour cut-out: 1314.05,616.29 1306.67,608.92 1306.67,607 1311.27,602.4 1319.14,602.4 1323.54,606.8
  pour cut-out: 993.94,838 993.84,837.9 993.84,831 1007.26,831 1007.36,831.1 1007.36,838
  pour cut-out: 1023.95,2497.21 1030.97,2497.21 1030.97,2484.87 1031.15,2484.69 1024.13,2484.69 1024.13,2497.03
  pour cut-out: 1457.35,956.2 1424.75,956.2 1424.75,993.5 1457.35,993.5 1457.35,956.2
  pour cut-out: 1861.25,1336.6 1826.95,1336.6 1826.95,1370.9 1861.25,1370.9 1861.25,1336.6
  pour cut-out: 1465.5,1470.43 1430.8,1470.43 1430.8,1503.03 1465.5,1503.03 1465.5,1470.43
  pour cut-out: 1898.45,967 1859.95,967 1859.95,1001.5 1898.45,1001.5 1898.45,967
  pour cut-out: 2558.87,1742.76 2558.26,1745.83 2556.52,1748.44 2553.91,1750.18 2550.84,1750.79 2547.77,1750.18 2545.16,1748.44 2543.42,1745.83 2542.81,1742.76 2543.42,1739.69 2545.16,1737.08 2547.77,1735.34 2550.84,1734.73 2553.91,1735.34 2556.52,1737.08 2558.26,1739.69 2558.87,1742.76
  pour cut-out: 2558.87,1691.58 2558.26,1694.65 2556.52,1697.26 2553.91,1699 2550.84,1699.61 2547.77,1699 2545.16,1697.26 2543.42,1694.65 2542.81,1691.58 2543.42,1688.51 2545.16,1685.9 2547.77,1684.16 2550.84,1683.55 2553.91,1684.16 2556.52,1685.9 2558.26,1688.51 2558.87,1691.58
  pour cut-out: 2558.87,1640.4 2558.26,1643.47 2556.52,1646.08 2553.91,1647.82 2550.84,1648.43 2547.77,1647.82 2545.16,1646.08 2543.42,1643.47 2542.81,1640.4 2543.42,1637.33 2545.16,1634.72 2547.77,1632.98 2550.84,1632.37 2553.91,1632.98 2556.52,1634.72 2558.26,1637.33 2558.87,1640.4
  pour cut-out: 2558.87,1589.22 2558.26,1592.29 2556.52,1594.9 2553.91,1596.64 2550.84,1597.25 2547.77,1596.64 2545.16,1594.9 2543.42,1592.29 2542.81,1589.22 2543.42,1586.15 2545.16,1583.54 2547.77,1581.8 2550.84,1581.19 2553.91,1581.8 2556.52,1583.54 2558.26,1586.15 2558.87,1589.22
  pour cut-out: 2507.69,1486.86 2507.08,1489.93 2505.34,1492.54 2502.73,1494.28 2499.66,1494.89 2496.59,1494.28 2493.98,1492.54 2492.24,1489.93 2491.63,1486.86 2492.24,1483.79 2493.98,1481.18 2496.59,1479.44 2499.66,1478.83 2502.73,1479.44 2505.34,1481.18 2507.08,1483.79 2507.69,1486.86
  pour cut-out: 2456.51,1486.86 2455.9,1489.93 2454.16,1492.54 2451.55,1494.28 2448.48,1494.89 2445.41,1494.28 2442.8,1492.54 2441.06,1489.93 2440.45,1486.86 2441.06,1483.79 2442.8,1481.18 2445.41,1479.44 2448.48,1478.83 2451.55,1479.44 2454.16,1481.18 2455.9,1483.79 2456.51,1486.86
  pour cut-out: 1719.75,1462.5 1590.75,1462.5 1590.75,1496.5 1720.75,1496.5 1721.75,1495.5 1721.75,1464.5 1719.75,1462.5
  pour cut-out: 1689.26,1378.31 1618.71,1378.31 1618.71,1409.91 1689.26,1409.91 1689.26,1378.31
  pour cut-out: 2079.35,1304.1 2051.05,1304.1 2050.2,1304.95 2050.2,1305.05 2042.75,1312.5 2042.75,1335 2025.25,1352.5 2005.25,1352.5 1995.25,1342.5 1936.75,1342.5 1911.25,1368 1911.25,1379.1 1901.45,1388.9 1891.65,1388.9 1886.15,1394.4 1886.15,1407.3 1890.15,1411.3 1899.75,1413 1902.15,1413.3 1901.95,1413.5 1900.75,1417.5 1900.75,1536.7 1914.05,1550 2107.75,1550 2128.5,1529.25 2121,1529.25 2105.25,1545 1922.48,1545 1912.75,1535.27 1912.75,1400 1965.25,1347.5 1992.75,1347.5 2002.75,1357.5 2027.75,1357.5 2047.75,1337.5 2047.75,1315 2052.75,1310 2077.75,1310 2110.25,1342.5 2110.25,1422.5 2147.75,1460 2152.75,1460 2154,1458.75 2115.25,1420 2115.25,1340 2079.35,1304.1
  pour cut-out: 1778.75,1240.5 1744.75,1240.5 1744.75,1272.5 1778.75,1272.5 1778.75,1240.5
  pour cut-out: 1878.75,1238.5 1844.75,1238.5 1844.75,1270.5 1878.75,1270.5 1878.75,1238.5
  pour cut-out: 1699.96,1226.44 1605.96,1226.44 1605.96,1260.44 1699.96,1260.44 1699.96,1226.44
  pour cut-out: 1566.81,1219.5 1534.69,1219.5 1534.69,1253.49 1566.81,1253.49 1566.81,1219.5
  pour cut-out: 1686.75,1052.5 1624.75,1052.5 1622.75,1054.5 1622.75,1088.5 1686.75,1088.5 1686.75,1052.5
  pour cut-out: 1714.75,964.5 1588.75,964.5 1588.75,998.5 1714.75,998.5 1714.75,964.5
  pour cut-out: 1293.95,2337.79 1293.95,2335.79 1298.04,2331.7 1293.3,2326.96 1291.72,2326.96 1291.72,2325.39 1288.55,2322.21 1284.46,2326.3 1284.46,2330.76 1291.49,2337.79
  pour cut-out: 2369.81,2242.61 2376.95,2242.61 2376.95,2229.19 2370.05,2229.19 2366.82,2232.42 2366.82,2239.62
  pour cut-out: 2296.73,1703.89 2300.48,1707.64 2302.54,1707.64 2302.54,1707.34 2309.88,1700 2305.84,1695.96 2301.2,1695.96 2301.2,1700.12 2297.43,1703.89
  pour cut-out: 2122.75,518.46 2128.71,512.5 2134.71,512.5 2139.75,517.54 2139.75,519 2135.15,523.6 2127.89,523.6
  pour cut-out: 1164.04,659.3 1164.04,653.4 1162.74,652.1 1169.45,652.1 1170.56,653.22 1170.56,657.26 1168.52,659.3
  pour cut-out: 1177.46,659.3 1177.46,647.51 1176.95,647 1175.66,647 1169.54,653.12 1169.54,658.28 1171.43,658.28 1173.15,660 1176.76,660
  text "LAYER-2 GND1" at -1293.22,-1034.39 h75
L3-GND/SIG:
  drawing of 85 lines, arcs and shapes, not listed
  text "LAYER-3 GND/SIGNAL" at -1349.73,-1034.31 h75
